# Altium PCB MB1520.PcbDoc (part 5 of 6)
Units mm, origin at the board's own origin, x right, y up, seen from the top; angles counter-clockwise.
Board outline 159 x 88 mm, 6 copper layers (Top Layer, Signal Layer 1, Signal Layer 2, Signal Layer 3, Signal Layer 4, Bottom Layer), stack 1.572 mm thick; 473 components, 377 nets, 1832 pads, 1378 vias.
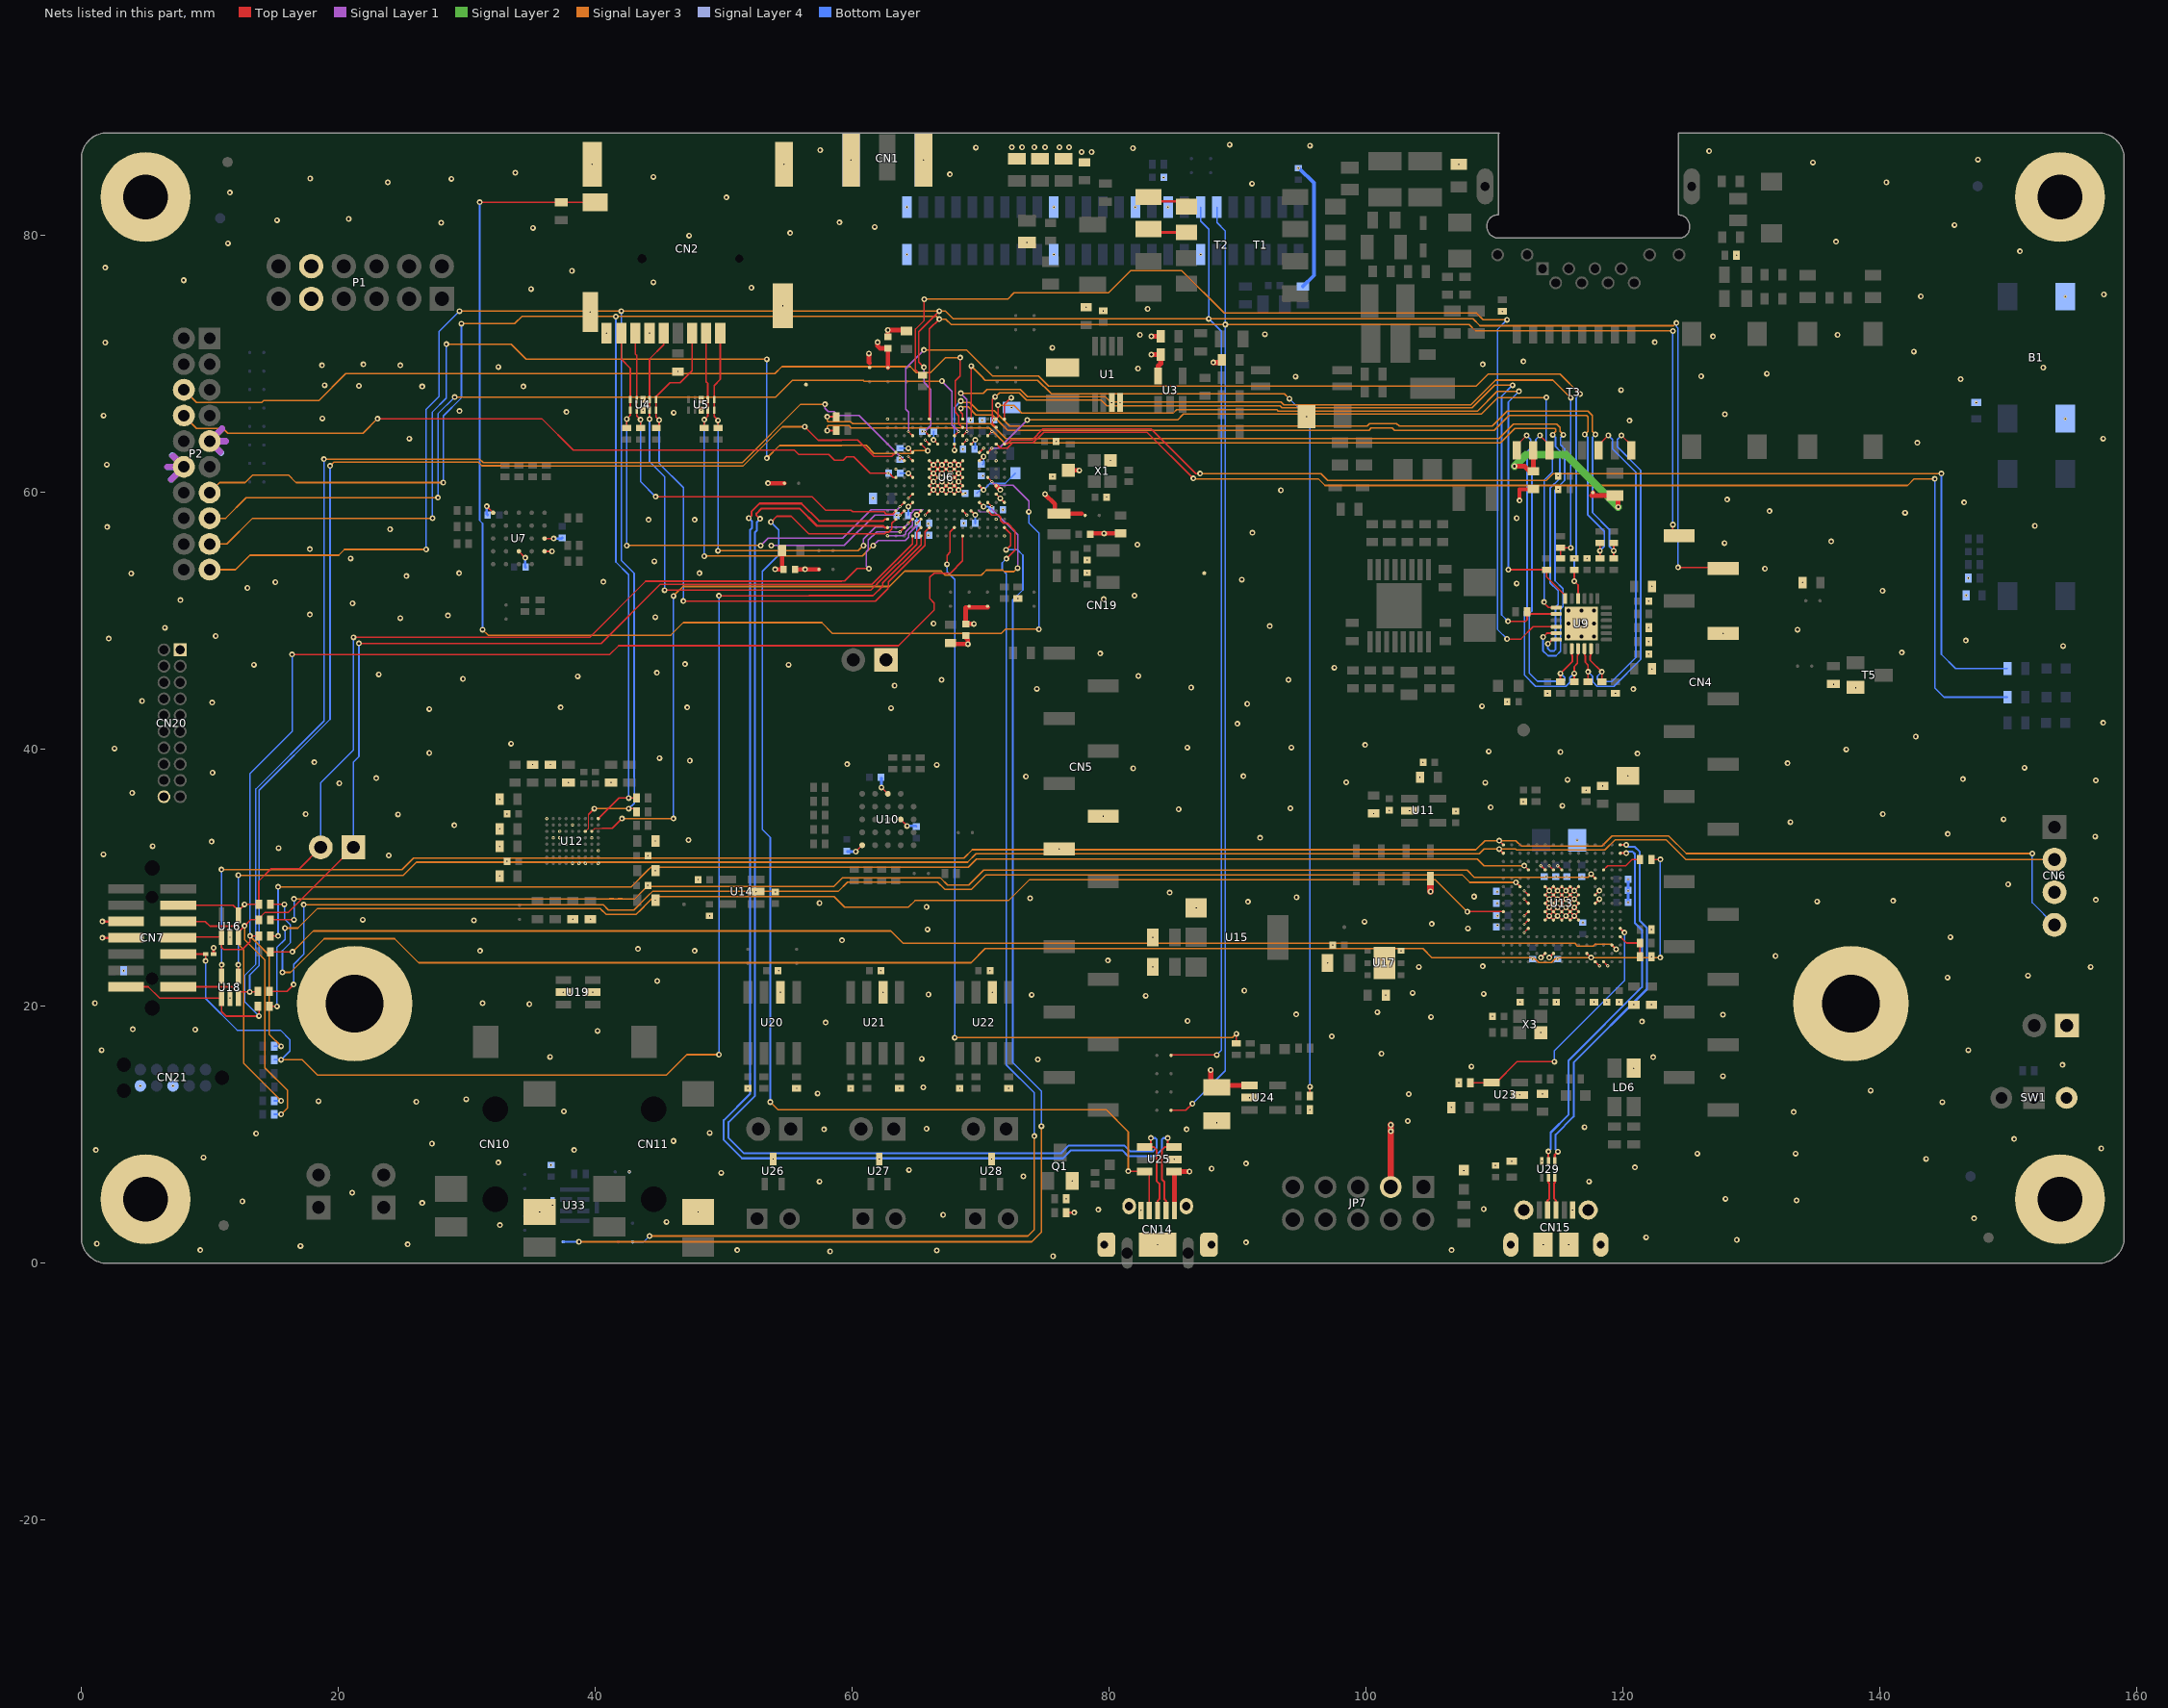
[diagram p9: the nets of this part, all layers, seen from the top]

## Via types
v1: diameter 0.45, hole 0.2, Top Layer to Bottom Layer, tented both sides, 1099 vias
v2: diameter 0.25, hole 0.1, Top Layer to Signal Layer 1, tented both sides, 217 vias
v3: diameter 0.25, hole 0.1, Signal Layer 4 to Bottom Layer, tented both sides, 53 vias
v4: diameter 0.6, hole 0.3, Top Layer to Bottom Layer, tented both sides, 9 vias

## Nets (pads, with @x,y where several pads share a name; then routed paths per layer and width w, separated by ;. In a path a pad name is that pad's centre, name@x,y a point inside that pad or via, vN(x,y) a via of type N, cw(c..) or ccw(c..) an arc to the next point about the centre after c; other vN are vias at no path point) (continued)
POE7: B1.1 B1.2 C3.1 C4.1 C5.1 C6.1 C11.1 C21.1 C22.1 C23.2 C24.2 C25.2 C26.1 C30.2 C32.1 C33.1 C34.2 C35.1 C36.2 C37.1 C38.1 C43.1 C44.1 C45.1 C46.2 C47.2 C48.1 C49.1 C50.1 C51.1 C53.1 C54.2 C55.2 C56.1 C61.2 C62.1 C63.1 C65.1 C66.1 C67.1 C70.1 C71.1 C72.1 C73.2 C74.1 C75.1 C76.1 C77.2 C78.2 C79.1 C80.1 C81.2 C82.2 C83.1 C84.1 C85.1 C86.2 C87.1 C88.1 C91.1 C92.1 C93.1 C94.1 C95.2 C96.1 C97.1 C98.1 C99.1 C100.1 C101.1 C102.1 C103.1 C104.1 C105.1 C106.1 C107.1 C108.1 C109.1 C110.1 C111.1 C112.2 C113.1 C114.1 C115.1 C116.2 C117.1 C120.1 C121.1 C122.1 C123.2 C124.1 C125.1 C126.1 C127.1 C128.1 C129.1 C130.2 C131.1 C132.1 C133.1 C134.1 C135.1 C136.1 C137.1 C139.1 C140.1 C141.1 C142.1 C143.1 C144.1 C145.1 C146.1 C147.1 C148.1 C149.1 C150.1 C151.1 C152.1 C153.1 C154.1 C155.1 C156.1 C157.1 C158.2 CN1.2 CN1.3 CN1.4 CN1.5 CN2.6 CN2.9 CN2.11 CN2.12 CN2.13 CN2.14 CN4.7 CN5.6 CN5.7 CN6.3 CN7.5 CN7.7 CN10.3 CN11.3 CN14.5 CN14.6 CN14.7 CN14.8 CN14.9 CN14.10 CN15.5 CN15.6 CN15.7 CN15.8 CN15.9 CN15.10 CN15.11 CN19.1 CN19.2 CN19.19 CN19.20 CN19.30 CN19.34 CN19.37 CN19.PTH1 CN19.PTH2 CN20.1 CN20.20 CN21.3 CN21.5 H1.1 H2.1 H3.1 H4.1 JP3.1 LD5.2 LD6.1 P1.5 P1.11 P2.5 P2.16 Q1.2 R1.2 R6.1 R13.1 R16.1 R19.2 R21.1 R57.2 R64.1 R70.2 R71.1 R73.2 R80.2 R84.1 R85.1 R89.1 R105.1 R109.1 R113.2 R120.2 R122.2 R124.2 R127.2 R129.1 R133.2 R137.1 R142.1 R146.1 SB35.1 SW1.3 T1.5 T1.6 T2.7 T2.8 T5.2 TP1.1 TP2.1 U1.7 U1.8 U3.5 U4.3 U4.8 U5.3 U5.8 U6.A1 U6.A15 U6.C2 U6.D6 U6.D10 U6.E1 U6.F2 U6.F6 U6.F7 U6.F8 U6.F9 U6.F10 U6.F12 U6.G6 U6.G7 U6.G8 U6.G9 U6.G10 U6.H6 U6.H7 U6.H8 U6.H9 U6.H10 U6.J6 U6.J7 U6.J8 U6.J9 U6.J10 U6.J14 U6.K2 U6.K6 U6.K7 U6.K8 U6.K9 U6.K10 U6.K12 U6.L4 U6.M6 U6.M10 U6.N3 U6.R1 U6.R15 U7.B1 U7.B3 U7.C1 U7.E5 U9.EP U10.B3 U10.C1 U10.E5 U11.2 U12.A1 U12.A3 U12.A4 U12.A5 U12.C1 U12.D6 U12.E2 U12.E7 U12.E8 U12.F7 U12.G5 U12.H9 U13.D5 U13.D6 U13.D7 U13.D8 U13.D9 U13.F2 U13.F6 U13.F7 U13.F8 U13.F9 U13.F10 U13.F12 U13.G2 U13.G6 U13.G7 U13.G8 U13.G9 U13.G10 U13.G12 U13.H6 U13.H7 U13.H8 U13.H9 U13.H10 U13.H12 U13.J6 U13.J7 U13.J8 U13.J9 U13.J10 U13.K6 U13.K7 U13.K8 U13.K9 U13.K10 U13.M1 U13.M8 U13.M9 U13.N1 U14.2 U15.1 U16.2 U17.6 U17.EP U18.2 U19.2 U19.5 U20.2 U21.2 U22.2 U23.2 U24.2 U25.2 U26.3 U27.3 U28.3 U29.3 U30.2 U31.2 U32.2 U33.5 U34.2 X1.2 X3.2 | length 138.7
  Top Layer w0.1: U6.R1@71.85,65.725 71.85,66.85 v1(72.375,67.375)
  Top Layer w0.12: v2(112.308,25.752) U13.D5@112.633,26.077 ; v2(112.308,26.402) U13.D6@112.633,26.727 ; v2(112.308,27.052) U13.D7@112.633,27.377 ; v2(112.308,28.352) U13.D8@112.633,28.027 ; v2(112.308,29.002) U13.D9@112.633,28.677 ; v1(113.608,23.802) U13.F2@113.933,24.127 ; v2(113.608,30.952) U13.F12@113.933,30.627 ; U13.F6@113.933,26.727 U13.G7@114.583,27.377 ; U13.F10@113.933,29.327 v1(114.258,29.002) U13.G9@114.583,28.677 ; v1(114.258,23.802) U13.G2@114.583,24.127 ; v2(114.258,30.952) U13.G12@114.583,30.627 ; v2(114.908,30.952) U13.H12@115.233,30.627 ; U13.K8@116.533,28.027 v1(116.208,28.352) U13.J9@115.883,28.677 ; U13.K10@116.533,29.327 U13.J9@115.883,28.677 ; U13.K6@116.533,26.727 v1(116.208,27.052) U13.J7@115.883,27.377 ; U13.K8@116.533,28.027 U13.J7@115.883,27.377 ; U13.M1@117.833,23.477 v2(118.158,23.152) ; U13.M8@117.833,28.027 v1(118.158,28.352) ; U13.M9@117.833,28.677 v1(118.158,29.002) ; U13.N1@118.483,23.477 v2(118.808,23.152) ; U13.G7@114.583,27.377 v1(114.908,27.052) U13.H6@115.233,26.727 U13.J7@115.883,27.377 ; U13.G7@114.583,27.377 v1(114.258,27.702) U13.F8@113.933,28.027 U13.G9@114.583,28.677 ; U13.G7@114.583,27.377 U13.H8@115.233,28.027 ; U13.G8@114.583,28.027 U13.F7@113.933,27.377 v1(114.258,27.052) U13.G6@114.583,26.727 U13.H7@115.233,27.377 ; U13.G8@114.583,28.027 v1(114.908,27.702) U13.H7@115.233,27.377 ; U13.G8@114.583,28.027 U13.H9@115.233,28.677 ; U13.G8@114.583,28.027 v1(114.258,28.352) U13.F9@113.933,28.677 U13.G10@114.583,29.327 v1(114.908,29.002) U13.H9@115.233,28.677 ; U13.G9@114.583,28.677 v1(114.908,28.352) U13.H8@115.233,28.027 ; U13.G9@114.583,28.677 U13.H10@115.233,29.327 v1(115.558,29.002) U13.J9@115.883,28.677 ; U13.H7@115.233,27.377 v1(115.558,27.052) U13.J6@115.883,26.727 U13.K7@116.533,27.377 v1(116.208,27.702) U13.J8@115.883,28.027 ; U13.H7@115.233,27.377 U13.J8@115.883,28.027 ; U13.H8@115.233,28.027 v1(115.558,27.702) U13.J7@115.883,27.377 ; U13.H8@115.233,28.027 U13.J9@115.883,28.677 ; U13.H9@115.233,28.677 v1(115.558,28.352) U13.J8@115.883,28.027 ; U13.H9@115.233,28.677 U13.J10@115.883,29.327 v1(116.208,29.002) U13.K9@116.533,28.677 U13.J8@115.883,28.027
  Top Layer w0.127: v1(31.55,58.925) U7.E5@32.05,58.425 ; U7.B3@34.05,55.425 v1(34.55,54.925) ; U7.B1@36.05,55.425 v1(36.625,55.425) ; U7.C1@36.05,56.425 v1(36.75,56.425) ; C47.2@54.55,54.125 C47.2@54.65,54.025 ; v1(60.275,32.05) U10.E5@60.775,32.55 ; v1(62.275,37.05) U10.C1@62.775,36.55 ; v2(62.745,56.629) U6.A15@62.75,56.625 ; U10.B3@63.775,34.55 v1(64.275,34.05) ; v2(64.375,59.55) U6.F12@64.7,59.875 ; v2(64.375,62.8) U6.K12@64.7,62.475 ; v2(65.675,58.25) U6.D10@66,58.575 ; v2(65.675,64.1) U6.M10@66,63.775 ; U6.F10@66,59.875 v1(66.325,60.2) ; U6.K10@66,62.475 v1(66.325,62.15) ; U6.F8@67.3,59.875 v1(66.975,60.2) ; U6.F8@67.3,59.875 v1(67.625,60.2) ; U6.G8@67.3,60.525 v1(67.625,60.2) ; U6.D6@68.6,58.575 v2(68.925,58.25) ; U6.F6@68.6,59.875 v1(68.275,60.2) ; U6.K6@68.6,62.475 v1(68.275,62.15) ; U6.M6@68.6,63.775 v2(68.925,64.1) ; U6.L4@69.9,63.125 v2(70.225,63.45) ; U6.N3@70.55,64.425 v2(70.875,64.75) ; U6.F2@71.2,59.875 v1(71.525,59.55) U6.E1@71.85,59.225 ; C43.1@78.525,56.75 C43.1@78.6,56.825 ; v1(66.325,60.2) U6.F9@66.65,59.875 v1(66.975,60.2) ; v1(66.325,60.2) U6.G10@66,60.525 v1(66.325,60.85) ; v1(66.325,60.2) U6.G9@66.65,60.525 ; v1(66.325,60.85) v1(66.975,61.5) ; v1(66.325,60.85) U6.G9@66.65,60.525 ; v1(66.325,60.85) U6.H10@66,61.175 v1(66.325,61.5) ; v1(66.325,61.5) v1(66.975,62.15) ; v1(66.325,61.5) U6.J10@66,61.825 v1(66.325,62.15) ; v1(66.325,61.5) v1(66.975,60.85) ; v1(66.325,62.15) U6.K9@66.65,62.475 v1(66.975,62.15) ; v1(66.325,62.15) v1(66.975,61.5) ; U6.G9@66.65,60.525 v1(66.975,60.85) ; U6.G9@66.65,60.525 v1(66.975,60.2) ; v1(66.975,60.2) U6.G8@67.3,60.525 ; v1(66.975,60.85) v1(67.625,61.5) ; v1(66.975,60.85) U6.G8@67.3,60.525 ; v1(66.975,61.5) v1(67.625,62.15) ; v1(66.975,61.5) v1(67.625,60.85) ; v1(66.975,62.15) v1(67.625,61.5) ; v1(66.975,62.15) U6.K8@67.3,62.475 v1(67.625,62.15) ; U6.G8@67.3,60.525 v1(67.625,60.85) ; v1(67.625,60.2) U6.F7@67.95,59.875 v1(68.275,60.2) ; v1(67.625,60.2) U6.G7@67.95,60.525 ; v1(67.625,60.85) U6.G7@67.95,60.525 ; v1(67.625,60.85) U6.H7@67.95,61.175 ; v1(67.625,61.5) U6.H7@67.95,61.175 ; v1(67.625,61.5) U6.J7@67.95,61.825 ; v1(67.625,62.15) U6.J7@67.95,61.825 ; v1(67.625,62.15) U6.K7@67.95,62.475 v1(68.275,62.15) ; U6.G7@67.95,60.525 v1(68.275,60.85) ; U6.G7@67.95,60.525 v1(68.275,60.2) ; U6.H7@67.95,61.175 v1(68.275,61.5) ; U6.H7@67.95,61.175 v1(68.275,60.85) ; U6.J7@67.95,61.825 v1(68.275,62.15) ; U6.J7@67.95,61.825 v1(68.275,61.5) ; v1(68.275,60.2) U6.G6@68.6,60.525 v1(68.275,60.85) ; v1(68.275,60.85) U6.H6@68.6,61.175 v1(68.275,61.5) ; v1(68.275,61.5) U6.J6@68.6,61.825 v1(68.275,62.15)
  Top Layer w0.2: v1(1.629,25.339) CN7.7@3.479,25.339 ; v1(1.629,26.609) CN7.5@3.479,26.609 ; U34.2@10.287,24.075 v1(10.287,24.563) ; T2.7@83.05,80.505 83.3,80.255 T1.6@86.023,80.255 ; T2.8@83.05,83.005 83.381,82.674 85.604,82.674 T1.5@86.023,82.255
  Top Layer w0.3: C25.2@88.547,70.125 C25.2@88.761,70.339 ; v1(111.95,59.375) 111.95,60.264 C33.1@113.011,60.264
  Top Layer w0.35: v1(54,54.025) C47.2@54.65,54.025 ; C47.2@54.55,54.125 C44.1@54.55,55.475 ; C23.2@62.775,72.125 v1(62.775,72.65) 64.15,72.65 C22.1@64.225,72.575 ; C53.1@67.65,48.3 67.55,48.2 v1(69,48.2) 69,48.55 68.85,48.7 C54.2@68.85,48.886 ; C43.1@78.6,56.825 C38.1@80.875,56.825
  Top Layer w0.4: v1(83.286,70.739) R21.1@84.011,70.739 84.011,70.036 83.811,69.836 U3.5@83.811,69.064 ; v1(83.286,72.164) R19.2@84.011,72.164 ; v1(88.1,70.125) C25.2@88.547,70.125
  Signal Layer 1 w0.09: 69.779,58.675 69.929,58.525 70.525,58.525
  Signal Layer 1 w0.1: v2@62.775,56.625 63.975,56.625 64.15,56.8 64.15,56.925 64.7,57.475 64.7,57.85 64.575,57.975 64.575,58.375 64.845,58.645 65.48,58.645 65.5,58.625
  Signal Layer 1 w0.5: 6.7,62 P2.16@7.975,62 ; 7,61.025 P2.16@7.975,62 ; 7.15,62.825 P2.16@7.975,62 ; 10.8,63.175 P2.5@9.975,64 ; 10.95,64.975 P2.5@9.975,64 ; 11.25,64 P2.5@9.975,64
  Signal Layer 4 w0.5: 6.75,62 P2.16@7.975,62 ; 7,61.025 P2.16@7.975,62 ; 7.075,62.9 P2.16@7.975,62 ; 10.875,63.1 P2.5@9.975,64 ; 10.95,64.975 P2.5@9.975,64 ; 11.2,64 P2.5@9.975,64
  Bottom Layer w0.127: C143.1@59.575,32.1 C143.1@59.625,32.05 ; C140.1@62.225,37.825 C140.1@62.275,37.775 ; C141.1@64.95,34.05 C141.1@65,34
  Bottom Layer w0.2: v1(31.55,58.925) 31.55,58.325 C132.1@31.625,58.25 ; v1(34.55,54.925) 34.55,54.215 C139.1@34.575,54.19 ; v1(36.75,56.425) 37.375,56.425 C136.1@37.425,56.475 ; C143.1@59.625,32.05 v1(60.275,32.05) ; v1(62.275,37.05) C140.1@62.275,37.775 ; v1(64.275,34.05) C141.1@64.95,34.05 ; v3(120.4,28.1) v3(120.4,29) C149.1@120.4,29.025 v3(120.4,29.875)
  Bottom Layer w0.3: v3(94.725,85.25) 94.78,85.25 95.925,84.105 95.925,76.9 R137.1@95.075,76.05
  other v1: 75.625,0.55 58.275,0.925 66.575,1 9.25,1.025 51.05,1.025 106.65,1.025 17.05,1.35 25.4,1.475 1.2,1.525 90.65,1.625 128.85,1.825 121.8,2.025 32.575,2.975 45.55,3.225 147.325,3.5 67.075,3.775 79.15,4.175 109.15,4.225 26.525,4.7 12.525,4.825 133.5,4.9 127.975,5.025 21.075,5.5 57.45,6.375 117.35,6.375 73.325,6.775 49.8,7.05 64.425,7.275 87.975,7.375 120.925,7.475 90.65,7.775 32.45,7.85 143.593,8.133 9.5,8.25 125.775,8.55 133.425,8.55 1.125,8.825 38.35,8.825 157.225,8.95 27.275,9.325 46.075,9.525 150.45,9.675 13.6,10.1 48.9,10.15 57.8,10.425 86.025,10.425 65.775,10.475 117,10.6 103.25,11.075 133.275,11.775 37.55,11.825 144.85,12.55 26.075,12.575 18.45,12.625 29.95,12.775 103.325,13.175 57.3,13.225 139.275,13.45 65.525,13.7 127.775,14.575 108.2,15.325 154.2,15.45 74.45,15.875 65.4,15.925 122.35,16.05 36.475,16.075 101.2,16.325 1.575,16.6 146.875,16.6 97.325,17.675 40.175,18.1 8.85,18.2 4,18.225 57.925,18.75 121.475,18.825 86.1,18.875 105.05,19.175 127.775,19.35 94.55,19.375 100.875,19.55 34.875,20.175 1.05,20.25 31.225,20.25 82.85,20.825 73.975,20.9 65.925,20.925 109.15,20.975 103.625,21.05 90.525,21.225 44.825,21.975 145.25,22.25 151.525,22.4 104.1,23.075 156.4,23.075 109.075,23.125 79.9,23.575 131.875,23.925 31.025,24.325 47.725,24.325 43.325,24.475 59.2,25.15 145.475,25.4 65.85,26 107.925,26.075 105.1,26.425 99.875,26.6 30.55,26.7 21.9,26.75 65.775,27.75 57.45,28.05 90.8,28.15 135.1,28.175 141.025,28.225 156.8,28.3 73.85,28.425 94.575,28.5 108.4,28.55 84.7,28.85 149.975,29.5 23.925,31.75 1.711,31.839 15.35,32.325 5.55,32.475 10.125,32.825 47.25,32.95 91.75,33.125 156.75,33.225 145.275,33.425 29.025,34.1 133.025,34.35 149.625,34.575 24.65,34.95 17.45,34.975 140.225,34.975 85.4,35.35 94.1,35.425 109.7,35.5 115.275,35.625 3.95,36.625 20.075,37.375 109.275,37.425 98.45,37.45 156.8,37.6 115.675,37.65 146.45,37.7 22.95,37.775 73.525,37.9 90.45,37.925 10.2,38.2 81.875,38.525 151.25,38.575 66.575,38.8 59.6,38.85 132.8,38.925 18.125,39 47.35,39.125 45,39.325 121.125,39.675 27.075,39.725 115.125,39.8 109.55,39.85 137.375,40 2.575,40.075 86.075,40.15 94.175,40.15 99.925,40.35 33.45,40.45 142.775,41 89.975,42 157.375,42.075 27.075,43.15 63.025,43.225 37.3,43.275 47.15,43.275 109.025,43.375 90.75,43.55 10.175,43.65 4.725,43.775 120.8,44.7 74.375,44.725 86.375,44.825 63.3,44.975 66.95,45.425 93.95,45.425 29.7,45.5 38.625,45.7 82.275,45.725 23.15,45.85 44.8,45.975 97.525,46.375 13.425,46.6 55.05,46.6 46.975,46.65 79.3,47.475 141.7,47.55 154.25,48.05 146.675,48.475 2.125,48.625 10.45,48.825 133.575,49.325 6.5,49.475 92.5,49.6 66.325,49.8 24.825,50.225 44.675,50.3 28.525,50.425 17.775,50.5 21.1,51.375 7.7,51.625 79.575,51.7 81.975,51.975 140.2,52.35 12.925,52.575 111.725,52.925 15.1,53.025 40.625,53.05 90.325,53.225 25.3,53.5 3.875,53.7 29.4,53.725 48.1,53.725 131.05,54.075 44.6,54.65 20.95,54.875 17.775,55.6 82.2,55.95 127.9,56.075 136.2,56.2 79.6,56.825 91.15,56.875 24.025,57.15 2,57.325 152.05,57.4 44.15,57.875 47.725,57.875 111.725,58 141.95,58.425 131.4,58.55 146.55,59.225 128.1,59.45 93.375,60.175 1.975,62.175 142.9,63.875 25.525,64.2 157.375,64.2 120.5,65.6 18.75,65.775 1.725,66 127.925,66.1 46.1,66.225 37.75,66.275 29.425,66.35 119.85,67.975 26.525,68.25 34.4,68.25 21.6,68.3 18.925,68.35 146.275,68.825 94.5,69.025 126.075,69.05 131.2,69.25 82.25,69.65 152.7,69.725 32.45,69.775 18.725,69.9 24.825,69.9 21.95,69.975 109.075,69.975 112.25,70.2 142.625,70.975 75.575,71.275 1.85,71.675 122.475,71.7 127,72.15 82.4,72.275 136.7,72.275 92.125,72.325 83,74.3 143.175,75.275 157.425,75.425 35,75.85 52.15,75.95 44.525,76.375 7.95,76.525 38.175,77.25 1.85,77.5 150.9,78.775 11.4,79.4 136.575,79.525 47.3,80 55.175,80.2 35.15,80.6 61.75,80.675 145.8,80.825 28,81 59,81.025 15.225,81.2 20.8,81.3 50.2,82.975 11.55,83.35 91.125,84.05 23.85,84.15 140.5,84.15 28.8,84.425 17.8,84.45 44.525,84.575 67.6,84.775 33.775,84.9 134.775,85.7 147.625,85.925 77.85,86.5 78.625,86.5 126.7,86.575 57.5,86.65 81.85,86.8 69.625,86.85 72.425,86.875 73.225,86.875 74.175,86.875 75,86.875 76.125,86.875 76.875,86.875 95.625,87 89.375,87.075
  other v2: 83.775,1.45 113.775,1.45 115.775,1.45 35.675,4 48,4 82.475,4.125 116.075,4.15 76.65,5.025 77.125,6.425 107.611,7.227 110.061,7.614 111.336,7.964 113.686,7.964 85.05,8.1 53.85,8.125 62.1,8.125 70.85,8.125 88.375,10.937 95.625,11.95 106.636,12.139 90.925,12.9 111.961,13.114 113.725,13.2 51.875,13.625 55.675,13.625 59.875,13.625 63.675,13.625 68.375,13.625 72.175,13.625 107.211,14.064 120.836,15.189 113.611,17.964 109.836,19.214 120.836,20.139 122.211,20.139 111.986,20.339 114.811,20.339 117.736,20.339 118.736,20.339 119.686,20.339 11.561,20.639 101.525,20.875 37.5,21.1 39.8,21.1 54.41,21.1 62.41,21.1 70.91,21.1 54.275,22.775 62.225,22.775 70.725,22.775 83.4,23.075 97,23.375 101.425,23.375 122.211,23.864 102.725,24.325 97.4,24.775 83.4,25.375 11.561,25.389 122.211,25.989 38.25,26.8 39.625,26.8 48.9,27.05 86.775,27.675 44.675,28.275 54.025,28.9 52.525,28.925 44.1,29.425 48,29.875 32.55,30.15 44.675,30.575 38.225,31.125 38.725,31.125 39.225,31.125 40.225,31.125 33.125,31.3 44.1,31.725 40.225,32.125 76.112,32.26 32.55,32.45 37.725,32.625 44.675,32.875 36.725,33.125 37.225,33.125 39.725,33.125 37.225,33.625 32.55,33.825 38.225,34.125 36.225,34.625 79.541,34.8 33.125,34.975 100.586,35.014 106.986,35.189 103.386,35.239 101.811,35.264 112.236,35.939 32.55,36.125 117.111,36.839 118.411,37.164 37.9,37.425 41.225,37.425 104.186,37.839 120.381,37.95 35.125,38.825 36.5,38.825 104.436,38.989 110.975,43.725 114.125,44.375 119.4,44.375 138.111,44.814 136.386,45.064 122.25,46.275 122,47.425 122,48.4 127.8,49.024 122,49.475 122,51.55 72.9,51.75 122.25,52.7 133.975,53 78.275,53.75 78.275,54.75 116.2,54.875 117.2,54.875 71.85,56.625 71.2,57.925 79.8,59.65 114.95,60.25 75.6,61.25 114.95,61.3 63.4,61.825 71.2,62.475 80.1,62.5 75.875,63.975 62.75,65.725 95.359,65.91 43.725,66.415 48.25,66.415 80.2,67 80.85,67 43.725,67.235 48.25,67.235 46.425,69.425 40.875,72.4 44.225,72.4 39.6,74.05 110.6,74.1 79.536,74.139 78.211,74.439 54.6,74.55 128.832,78.483 73.611,79.464 39.75,85.55 54.7,85.55 107.211,85.539 59.9,85.9 65.55,85.9
  other v3: 36.674,4.523 42.649,7.123 36.549,7.648 4.585,13.815 7.125,13.815 3.286,22.789 112.975,23.675 114.9,23.675 110.225,26.325 116.875,26.525 110.225,27.05 110.211,28.014 110.211,28.914 114,30.1 114.8,30.1 115.6,30.1 116.8,30.1 116.425,32.925 146.7,52 146.875,53.35 65.925,56.675 65.925,57.575 68.675,57.6 63.45,58.225 71.725,58.65 61.625,59.55 68.8,59.95 70.175,61.3 62.825,61.5 63.7,62.55 68.625,63.375 65.45,64.775 69.2,65.625 70.125,65.625 71.025,65.625 154.425,65.75 72.4,66.625 147.5,67 154.425,75.25 64.26,78.531 75.69,78.531 87.12,78.531 64.26,82.217 75.69,82.217 82.04,82.217 84.58,82.217 84.25,84.525 59.9,85.9 65.55,85.9
  other v4: 115.75,48.8 116.75,48.8 117.75,48.8 115.75,49.8 116.75,49.8 117.75,49.8 115.75,50.8 116.75,50.8 117.75,50.8
RD_N: R78.1 T3.8 U9.22 | length 28.2
  Top Layer w0.13: U9.22@117,47.85 117,47.36 117.059,47.3 117.059,46.792 117.275,46.577 v1(117.275,46.05) R78.1@117.275,45.275 ; v1(119.875,64.45) 120.631,63.694 T3.8@120.631,63.279
  Bottom Layer w0.13: v1(117.275,46.05) 117.622,45.703 117.622,45.289 117.992,44.919 119.283,44.919 121.375,47.011 121.375,61.735 119.552,63.558 119.552,64.127 v1(119.875,64.45)
RD_P: R79.1 T3.6 U9.23 | length 27.2
  Top Layer w0.13: U9.23@117.5,47.85 117.5,47.36 117.44,47.3 117.44,46.95 v1(118.35,46.04) R79.1@118.35,45.275 ; T3.6@118.091,63.279 118.091,63.694 v1(118.848,64.45)
  Bottom Layer w0.13: v1(118.35,46.04) 118.003,45.693 118.003,45.447 118.15,45.3 119.125,45.3 120.994,47.169 120.994,61.577 119.171,63.4 119.171,64.127 v1(118.848,64.45)
RMII_CRS_DV: R51.2 R56.1 U6.N6 | length 66.4
  Top Layer w0.12: R56.1@115.125,54.875 R51.2@115.125,55.7 v1(115.925,55.7)
  Top Layer w0.127: U6.N6@68.6,64.425 v2(68.925,64.75)
  Signal Layer 1 w0.1: v1(68.45,67.725) 68.925,67.25 v2(68.925,64.75)
  Signal Layer 3 w0.1: v1(68.45,67.725) 70.175,67.725 70.475,68.025 73.061,68.025 73.636,67.45 75.425,67.45
  Signal Layer 3 w0.12: 75.425,67.45 79.7,67.45 80.1,67.05 93.375,67.05 93.594,66.831 108.154,66.831 110.078,68.755 114.545,68.755 v1(115.925,67.375)
  Bottom Layer w0.12: v1(115.925,55.7) v1(115.925,67.375)
RMII_MDC: U6.L3 U9.13 | length 62.8
  Top Layer w0.12: v1(113.85,51.475) 113.85,51.398 114.198,51.05 U9.13@114.8,51.05
  Top Layer w0.127: U6.L3@70.55,63.125 v2(70.875,63.45)
  Signal Layer 1 w0.1: v2(70.875,63.45) 71.425,63.45 v1(73.625,65.65)
  Signal Layer 3 w0.1: v1(73.625,65.65) 75.425,65.65
  Signal Layer 3 w0.12: 75.425,65.65 85.325,65.65 85.78,66.105 108.98,66.105 110.275,67.4 v1(114.025,67.4)
  Bottom Layer w0.12: v1(113.85,51.475) 113.85,60.95 114.5,61.6 114.5,62.575 114.025,63.05 v1(114.025,67.4)
RMII_MDIO: R55.1 U6.R2 U9.12 | length 62.7
  Top Layer w0.1: U6.R2@71.2,65.725 71.35,65.875 v1(71.35,66.8)
  Top Layer w0.12: v1(111.075,54) 114.025,54 R55.1@114.05,53.975 114.05,53.431 115.5,51.981 U9.12@115.5,51.75
  Signal Layer 3 w0.1: v1(71.35,66.8) 72.6,66.8 73.2,66.2 75.425,66.2
  Signal Layer 3 w0.12: 75.425,66.2 85,66.2 85.25,66.45 93.05,66.45 93.155,66.345 108.67,66.345 110.2,67.875 v1(111.9,67.875)
  Bottom Layer w0.12: v1(111.075,54) 111.075,67.05 v1(111.9,67.875)
RMII_REF_CLK: R67.2 U6.P2 U9.14 | length 67.7
  Top Layer w0.1: v1(71.125,67.45) 70.9,67.225 70.9,65.375 U6.P2@71.2,65.075
  Top Layer w0.127: v1(111.048,49.975) 112.425,49.975 112.525,50.075 R67.2@112.525,50.725 112.7,50.55 U9.14@114.8,50.55
  Signal Layer 3 w0.1: v1(71.125,67.45) 71.45,67.775 73,67.775 73.579,67.196
  Signal Layer 3 w0.102: 73.579,67.196 79.354,67.196 79.8,66.75 93.3,66.75 93.45,66.6 108.25,66.6 110,68.35 v1(111.4,68.35)
  Bottom Layer w0.127: v1(111.048,49.975) 110.55,50.473 110.55,67.5 v1(111.4,68.35)
RMII_RX_ER: R57.1 U6.N12 U9.10 | length 77.9
  Top Layer w0.12: R57.1@116.2,53.975 v1(116.2,53.1) 116.5,52.8 U9.10@116.5,51.75
  Top Layer w0.127: v2(64.375,64.75) U6.N12@64.7,64.425
  Signal Layer 1 w0.1: v2(64.375,64.75) 64.375,66.275 64.155,66.495 64.155,69.68 v1(65.575,71.1)
  Signal Layer 3 w0.1: 74.5,69.075 75.3,68.275 75.425,68.275
  Signal Layer 3 w0.12: v1(65.575,71.1) 68.9,71.1 70.925,69.075 74.5,69.075 ; 75.425,68.275 108.55,68.275 109.5,69.225 115.1,69.225 v1(116.65,67.675)
  Bottom Layer w0.12: v1(116.2,53.1) 116.2,54.925 116.35,55.075 116.35,67.375 v1(116.65,67.675)
RMII_RXD0: R49.1 R58.1 U6.R6 | length 63.7
  Top Layer w0.1: v1(68.45,66.55) 68.45,66.275 68.6,66.125 U6.R6@68.6,65.725
  Top Layer w0.13: R58.1@118.2,54.875 v1(118.2,55.475) R49.1@118.2,56.075
  Signal Layer 3 w0.104: v1(68.45,66.55) 68.572,66.672 69.025,66.672 69.647,66.05 70.9,66.05 72.106,64.844 100.212,64.844 100.393,65.025 102.019,65.025 102.2,64.844 109.962,64.844 111.118,66 117.15,66 117.269,65.881 117.269,64.775 v1(117.019,64.525)
  Bottom Layer w0.13: v1(117.019,64.525) 117.244,64.3 117.244,58.281 118.547,56.978 118.547,55.822 v1(118.2,55.475)
RMII_RXD1: R50.1 R59.1 U6.M7 | length 67.9
  Top Layer w0.1: v1(67.95,63.3) U6.M7@67.95,63.775
  Top Layer w0.13: R59.1@119.275,54.875 v1(119.275,55.475) R50.1@119.275,56.075
  Signal Layer 3 w0.104: v1(68.45,67.125) 68.572,67.003 69.162,67.003 69.784,66.381 71.037,66.381 72.243,65.175 100.075,65.175 100.275,65.375 102.375,65.375 102.575,65.175 109.825,65.175 110.981,66.331 117.287,66.331 117.6,66.018 117.6,64.775 v1(117.85,64.525)
  Bottom Layer w0.1: v1(67.95,63.3) 67.95,66.615 67.965,66.631 67.965,66.64 v1(68.45,67.125)
  Bottom Layer w0.13: v1(117.85,64.525) 117.625,64.3 117.625,58.439 118.928,57.136 118.928,55.822 v1(119.275,55.475)
RMII_TX_EN: R24.1 U9.16 | length 84.2
  Top Layer w0.12: R24.1@65.475,69.125 65.35,69.125 64.925,69.55 64.925,72.725 65.6,73.4 v1(65.6,75.05) ; v1(110.975,48.6) 112.05,48.6 113,49.55 U9.16@114.8,49.55
  Signal Layer 3 w0.12: v1@65.689,75.139 v1(65.6,75.05) 72.1,75.05 72.6,75.55 79.95,75.55 81.675,77.275 85.65,77.275 88.95,73.975 108.575,73.975 109.1,73.45 v1(110.975,73.45)
  Bottom Layer w0.12: v1(110.975,48.6) 110.216,49.359 110.216,72.691 v1(110.975,73.45)
RMII_TXD0: R25.1 U9.17 | length 81.5
  Top Layer w0.13: v1(58.05,65.9) R25.1@58.75,65.9 ; v1(113.775,48.75) 114.075,49.05 U9.17@114.8,49.05
  Signal Layer 3 w0.104: v1(58.05,65.9) 58.05,65.603 58.125,65.528 59.865,65.528 60.034,65.359 70.809,65.359 71.962,64.206 110.331,64.206 111.456,65.331 114.837,65.331 115.106,65.062 115.106,64.75 v1(115.356,64.5)
  Bottom Layer w0.13: v1(113.775,48.75) 113.76,48.735 113.76,47.701 114.167,47.294 114.783,47.294 115.131,47.642 115.131,50.931 115.331,51.131 115.331,52.508 115.325,52.514 114.703,53.136 114.703,60.189 115.456,60.942 115.456,63.394 115.131,63.719 115.131,64.275 v1(115.356,64.5)
RMII_TXD1: R32.1 U9.18 | length 78.8
  Top Layer w0.13: v1(58.05,64.825) R32.1@58.75,64.825 ; v1(114.15,48.225) 114.475,48.55 U9.18@114.8,48.55
  Signal Layer 3 w0.104: v1(58.05,64.825) 58.05,65.122 58.125,65.197 59.728,65.197 59.897,65.028 70.672,65.028 71.825,63.875 110.468,63.875 111.593,65 114.7,65 114.775,64.925 114.775,64.75 v1(114.525,64.5)
  Bottom Layer w0.13: v1(114.15,48.225) 114.15,47.85 114.325,47.675 114.625,47.675 114.75,47.8 114.75,51.089 114.95,51.289 114.95,52.35 114.322,52.978 114.322,60.347 115.075,61.1 115.075,63.236 114.75,63.561 114.75,64.275 v1(114.525,64.5)
SAI1_SD_A: U6.E3 U12.F2 | length 58.2
  Top Layer w0.09: U12.F2@39.725,33.625 39.975,33.875 40.55,33.875
  Top Layer w0.1: 40.55,33.875 41.325,33.875 v1(42.075,34.625)
  Top Layer w0.127: U6.E3@70.55,59.225 v2(70.875,58.9)
  Signal Layer 1 w0.1: v2(70.875,58.9) 70.875,58.7 72.875,56.7 v1(72.875,54.125)
  Signal Layer 3 w0.1: v1(42.075,34.625) 44.1,34.625
  Signal Layer 3 w0.12: 44.1,34.625 v1(46.075,34.625) ; v1(46.075,51.95) 46.814,52.689 62.889,52.689 64.085,53.885 66.92,53.885 67.23,53.575 70.05,53.575 70.435,53.96 71.715,53.96 71.83,53.845 72.595,53.845 v1(72.875,54.125)
  Bottom Layer w0.12: v1(46.075,34.625) v1(46.075,51.95)
SAI4_CK2: SB40.2 U6.D3 | length 90.4
  Top Layer w0.1: U6.D3@70.55,58.575 70.875,58.25 71.375,58.25 71.525,58.1 71.525,57.825 71.75,57.6 72.1,57.6 72.675,57.025 72.675,55.525 v1(72,54.85)
  Signal Layer 3 w0.12: v1(44.225,2.125) 73.675,2.125 74.175,2.625 v1(74.175,9.9)
  Bottom Layer w0.12: SB40.2@42.899,1.673 43.773,1.673 v1(44.225,2.125) ; v1(72,54.85) 71.675,54.525 71.675,54 71.998,53.676 71.998,15.452 74.175,13.275 v1(74.175,9.9)
SAI4_D2: SB39.2 U6.B1 | length 95
  Top Layer w0.1: U6.B1@71.85,57.275 72.325,56.8 72.325,55.9 v1(71.975,55.55)
  Signal Layer 3 w0.12: v1(38.725,1.675) 73.975,1.675 74.725,2.425 v1(74.725,10.675)
  Bottom Layer w0.12: SB39.2@37.5,1.675 v1(38.725,1.675) ; v1(71.975,55.55) 72.85,55.55 73.28,55.12 73.28,52.429 72.5,51.649 72.5,15.625 74.725,13.4 v1(74.725,10.675)
SCL: CN4.10 CN19.40 P2.7 R90.1 SB34.1 U6.R10 U12.H1 | length 265.7
  Top Layer w0.1: U12.H1@40.225,34.625 41.825,36.225 v1(42.6,36.225) R90.1@43.2,36.225 ; U6.R10@66,65.725 66.009,65.734 66.009,69.075
  Top Layer w0.12: 66.009,69.075 66.009,72.734 v1(66.775,73.5) ; SB34.1@84.811,11.914 85.964,11.914 v1(86.475,12.425) ; v1(123.875,57.5) 123.875,57.142 CN4.10@124.372,56.644
  Signal Layer 3 w0.12: P2.7@9.975,60 10.75,60.775 12.75,60.775 13.325,61.35 16.125,61.35 16.7,60.775 v1(28.167,60.775) ; v1(29.575,73.15) 33.725,73.15 34.3,73.725 41.72,73.725 41.725,73.72 66.555,73.72 v1(66.775,73.5) 67.275,73.5 67.695,73.08 v1(89.038,73.08) 108.02,73.08 108.52,72.58 v1(123.875,72.58)
  Bottom Layer w0.1: v1@42.6,36.25 42.6,37.8
  Bottom Layer w0.12: v1(28.167,60.775) 28.167,65.967 29.575,67.375 v1(29.575,73.15) ; v1(41.6,73.7) 41.6,54.6 42.6,53.6 42.6,37.8 ; v1(86.475,12.425) 89.038,14.988 v1(89.038,73.08) 89.038,80.361 88.39,81.009 CN19.40@88.39,82.217 ; v1(123.875,57.5) v1(123.875,72.58)
SDA: CN4.9 CN19.38 P2.10 R92.1 SB31.1 U6.N10 U12.F3 | length 281.2
  Top Layer w0.09: U12.F3@39.225,33.625 39.475,33.875 39.475,34.95
  Top Layer w0.1: 39.475,34.95 v1(39.925,35.4) ; v1(42.6,35.4) R92.1@43.2,35.4
  Top Layer w0.12: v1(65.575,69.75) 65.17,70.155 65.17,72.52 v1(66.775,74.125) ; SB31.1@84.811,16.189 84.847,16.225 v1(88.375,16.225) ; v1(124.28,54.17) 127.576,54.17 127.721,54.025 CN4.9@127.8,54.104
  Top Layer w0.127: v2(65.675,64.75) U6.N10@66,64.425
  Signal Layer 1 w0.1: v1(65.575,69.75) 65.575,68.575 66.125,68.025 66.125,65.2 v2(65.675,64.75)
  Signal Layer 3 w0.1: v1(39.925,35.4) v1(42.6,35.4)
  Signal Layer 3 w0.12: P2.10@9.975,54 12,54 13.125,55.125 16.298,55.125 20.025,55.125 20.475,55.575 v1(26.825,55.575) ; v1(29.425,74.125) v1(66.775,74.125) 67.25,74.125 67.85,73.525 v1(87.753,73.525) 108.326,73.525 108.866,72.985 123.935,72.985 v1(124.15,73.2)
  Bottom Layer w0.1: v1(42.6,35.4) 43.025,35.825 43.025,37.8
  Bottom Layer w0.12: v1(26.825,55.575) 26.825,66.475 27.85,67.5 27.85,72.55 v1(29.425,74.125) ; v1(42.025,74.125) 42.025,54.714 43.025,53.714 43.025,37.8 ; CN19.38@87.12,82.217 87.12,81.129 87.753,80.496 v1(87.753,73.525) 88.73,72.548 88.73,16.58 v1(88.375,16.225) ; v1(124.15,73.2) 124.15,72.93 124.28,72.8 v1(124.28,54.17)
SDIO1_CK: CN2.5 U4.2 U4.9 U6.B11 | length 43.5
  Top Layer w0.1: 61.929,52.879 65.025,55.975 65.025,56.95 U6.B11@65.35,57.275
  Top Layer w0.127: v1(44.225,65.725) U4.9@44.225,66.415 U4.2@44.225,67.235 44.225,70.4 45.325,71.5 CN2.5@45.325,72.4 ; v1(45.4,52.4) 61.45,52.4 61.929,52.879
  Bottom Layer w0.127: v1(44.225,65.725) 44.225,62.4 45.4,61.225 v1(45.4,52.4)
SDIO1_CMD: CN2.3 R29.1 U4.1 U4.10 U6.B10 | length 46.5
  Top Layer w0.1: 62.804,52.625 62.804,53.029 65.675,55.9 65.675,56.95 U6.B10@66,57.275
  Top Layer w0.127: R29.1@44.75,65.025 44.975,65.25 v1(44.975,65.65) 44.725,65.9 U4.10@44.725,66.415 U4.1@44.725,67.235 44.725,67.45 45.825,68.55 46.6,68.55 47.525,69.475 CN2.3@47.525,72.4 ; v1(46.854,51.546) 61.804,51.546 62.783,52.525 62.783,52.604 62.804,52.625
  Bottom Layer w0.127: v1(44.975,65.65) 44.975,62.254 46.854,60.375 v1(46.854,51.546)
SDIO1_D0: CN2.7 R28.1 U4.4 U4.7 U6.D14 | length 33.4
  Top Layer w0.1: 59.167,58.633 59.91,58.633 60.042,58.5 62.464,58.5 62.644,58.32 63.145,58.32 U6.D14@63.4,58.575
  Top Layer w0.127: CN2.7@43.125,72.4 43.125,70.775 43.225,70.675 U4.4@43.225,67.235 U4.7@43.225,66.415 43.225,65.975 v1(43.525,65.675) R28.1@43.525,65.025 ; v1(44.7,59.675) 56.884,59.675 57.926,58.633 59.167,58.633
  Bottom Layer w0.127: v1(43.525,65.675) 43.525,60.85 v1(44.7,59.675)
SDIO1_D1: CN2.8 R27.1 U4.5 U4.6 U6.E13 | length 40.6
  Top Layer w0.127: CN2.8@42.025,72.4 42.025,70.375 42.725,69.675 U4.5@42.725,67.235 U4.6@42.725,66.415 42.725,66 v1(42.45,65.725) R27.1@42.45,65.025 ; v2(63.725,58.9) U6.E13@64.05,59.225
  Signal Layer 1 w0.1: v1(52.875,55.875) 53.45,56.45 59.275,56.45 61.475,58.65 63.475,58.65 v2(63.725,58.9)
  Signal Layer 3 w0.102: v1(42.45,55.875) v1(52.875,55.875)
  Bottom Layer w0.127: v1(42.45,55.875) v1(42.45,65.725)
SDIO1_D2: CN2.1 R31.1 U5.1 U5.10 U6.C12 | length 34.3
  Top Layer w0.127: R31.1@49.55,65.025 v1(49.55,65.625) 49.25,65.925 U5.10@49.25,66.415 U5.1@49.25,67.235 49.25,68.325 49.725,68.8 CN2.1@49.725,72.4 ; v2(64.375,57.6) U6.C12@64.7,57.925
  Signal Layer 1 w0.1: v1(60.875,55.875) 60.875,56.378 61.822,57.325 64.1,57.325 v2(64.375,57.6)
  Signal Layer 3 w0.1: 59.175,55.473 60.473,55.473 v1(60.875,55.875)
  Signal Layer 3 w0.102: v1(49.55,55.473) 59.175,55.473
  Bottom Layer w0.127: v1@49.55,55.473 v1(49.55,65.625)
SDIO1_D3: CN2.2 R30.1 U5.2 U5.9 U6.C11 | length 36.5
  Top Layer w0.127: R30.1@48.475,65.025 v1(48.475,65.675) 48.75,65.95 U5.9@48.75,66.415 U5.2@48.75,67.235 48.75,68.5 48.625,68.625 CN2.2@48.625,72.4 ; v2(65.025,57.6) U6.C11@65.35,57.925
  Signal Layer 1 w0.1: v1(61.625,55.875) 62.027,56.277 64.136,56.277 64.378,56.519 64.378,56.784 65.025,57.431 v2(65.025,57.6)
  Signal Layer 3 w0.1: 59.175,55.05 60.8,55.05 v1(61.625,55.875)
  Signal Layer 3 w0.102: v1(48.475,55.05) 59.175,55.05
  Bottom Layer w0.127: v1(48.475,55.05) v1(48.475,65.675)
STLK_SWCLK: CN6.2 U13.A14 U18.4 | length 151.6
  Top Layer w0.12: U18.4@12.211,22.339 v1(12.211,23.236) ; v1(110.358,32.252) U13.A14@110.683,31.927
  Signal Layer 3 w0.12: v1(12.211,30.211) 25.061,30.211 26.075,31.225 33.2,31.225 44.1,31.225 68.975,31.225 69.625,31.875 108.8,31.875 109.177,32.252 109.908,32.252 v1(110.358,32.252) 111.623,32.252 111.7,32.175 118.586,32.175 119.386,32.975 120.558,32.975 123.35,32.975 124.898,31.427 CN6.2@153.581,31.427
  Bottom Layer w0.12: v1(12.211,23.236) v1(12.211,30.211)
STLK_SWDIO: CN6.4 U13.A15 U18.5 | length 158
  Top Layer w0.12: U18.5@10.911,22.339 v1(10.911,23.236) ; v1(110.358,32.902) U13.A15@110.683,32.577
  Signal Layer 3 w0.12: v1(10.9,30.65) 24.95,30.65 25.85,31.55 33.2,31.55 44.1,31.55 68.7,31.55 69.35,32.2 108.55,32.2 109.252,32.902 109.908,32.902 v1(110.358,32.902) 111.66,32.902 112.087,32.475 118.35,32.475 119.15,33.275 120.558,33.275 123.55,33.275 124.925,31.9 v1(151.85,31.9)
  Bottom Layer w0.12: v1(10.9,30.65) 10.911,30.639 v1(10.911,23.236) ; v1(151.85,31.9) 151.85,28.078 CN6.4@153.581,26.347
STLK_VCP_RX: R110.2 U13.C10 | length 105.5
  Top Layer w0.12: R110.2@14.625,21.175 16,21.175 v1(16.525,21.7) ; v1(111.658,29.652) U13.C10@111.983,29.327
  Signal Layer 3 w0.12: v1(17.3,27.925) 33.2,27.925 40.6,27.925 41.025,27.5 43,27.5 44.1,28.6 44.45,28.95 58.9,28.95 59.63,29.68 66.645,29.68 67.2,29.125 69.3,29.125 70.425,30.25 107.475,30.25 108.073,29.652 109.908,29.652 v1(111.658,29.652)
  Bottom Layer w0.12: v1(16.525,21.7) 16.525,23.275 17.3,24.05 v1(17.3,27.925)
STLK_VCP_TX: R114.1 U13.A7 | length 105.4
  Top Layer w0.12: R114.1@14.625,20 v1(15.225,20) ; v1(107.873,27.377) U13.A7@110.683,27.377
  Signal Layer 3 w0.12: v1(15.85,26.1) 16.85,26.1 18.35,27.6 33.2,27.6 40.4,27.6 40.5,27.5 40.825,27.175 43.2,27.175 43.525,27.5 44.1,28.075 44.575,28.55 58.575,28.55 59.4,27.725 64.375,27.725 64.889,28.239 72.164,28.239 73.775,29.85 105.4,29.85 v1(107.873,27.377)
  Bottom Layer w0.12: v1(15.225,20) 15.225,24.6 15.85,25.225 v1(15.85,26.1)
STMOD#8-MOSIs: P2.8 U6.N7 | length 70.2
  Top Layer w0.127: U6.N7@67.95,64.425 v2(68.275,64.75)
  Signal Layer 1 w0.1: v1(66.975,68.675) 67.775,67.875 67.775,65.25 v2(68.275,64.75)
  Signal Layer 3 w0.12: P2.8@9.975,58 11.225,58 12.825,59.6 v1(27.75,59.6) ; v1(29.05,67.425) 54.025,67.425 55.336,68.736 60.864,68.736 60.925,68.675 v1(66.975,68.675)
  Bottom Layer w0.12: v1(27.75,59.6) 27.75,66.125 v1(29.05,67.425)
STMOD#9-MISOs: P2.9 U6.M11 | length 79.3
  Top Layer w0.127: U6.M11@65.35,63.775 v1(65.875,63.25)
  Signal Layer 3 w0.1: 59.175,63.662 61.088,63.662 61.695,63.055 64.63,63.055 64.825,63.25 v1(65.875,63.25)
  Signal Layer 3 w0.12: P2.9@9.975,56 11.325,56 13.325,58 v1(27.325,58) ; v1(28.4,71.55) 33.45,71.55 34.625,70.375 v1(53.35,70.375) ; v1(53.35,62.675) 54.337,63.662 59.175,63.662
  Bottom Layer w0.12: v1(27.325,58) 27.325,66.275 28.4,67.35 v1(28.4,71.55) ; v1(53.35,62.675) v1(53.35,70.375)
STMOD#13-ADC: P2.13 U6.P6 | length 68.5
  Top Layer w0.1: 68.406,69.075 68.025,68.694 68.025,66.25 68.3,65.975 68.3,65.375 U6.P6@68.6,65.075
  Top Layer w0.127: 68.406,69.075 v1(68.406,70.5)
  Signal Layer 3 w0.1: P2.13@7.975,68 8.975,67 11.025,67
  Signal Layer 3 w0.12: 11.025,67 14.025,67 14.175,67.15 18.475,67.15 20.575,69.25 53.975,69.25 54.525,69.8 64.525,69.8 64.98,69.345 66.095,69.345 67.25,70.5 v1(68.406,70.5)
STMOD#14-PWM: P2.14 U6.H14 | length 58.6
  Top Layer w0.1: 59.175,62.525 59.295,62.525 59.545,62.775 60.125,62.775 61.4,61.5 62.875,61.5 63.2,61.175 U6.H14@63.4,61.175
  Top Layer w0.12: v1(23.05,65.75) 35.825,65.75 38.275,63.3 55.5,63.3 55.825,62.975 56.125,62.975
  Top Layer w0.127: 56.125,62.975 58.175,62.975 58.625,62.525 59.175,62.525
  Signal Layer 3 w0.1: P2.14@7.975,66 8.975,65 11.025,65
  Signal Layer 3 w0.12: 11.025,65 11.4,64.625 21.925,64.625 v1(23.05,65.75)
T_JTDI: CN7.10 R148.1 U6.A11 U34.1 | length 105
  Top Layer w0.1: 62.375,52.95 65.35,55.925 U6.A11@65.35,56.625
  Top Layer w0.12: CN7.10@7.543,24.069 7.549,24.075 U34.1@9.663,24.075 v1(9.663,23.538) ; v1(49.625,51.969) 56.621,51.969 56.625,51.973
  Top Layer w0.127: 56.625,51.973 61.627,51.973 62.356,52.702 62.356,52.931 62.375,52.95
  Signal Layer 3 w0.12: v1(15.55,15.85) 17.175,15.85 18.375,14.65 45.525,14.65 47.125,16.25 v1(49.625,16.25)
  Bottom Layer w0.12: v1(9.663,23.538) 9.663,20.612 12.125,18.15 15.5,18.15 16.234,17.416 16.234,16.534 v1(15.55,15.85) R148.1@15,15.85 ; v1(49.625,16.25) v1(49.625,51.969)
T_NRSTa: R108.2 U13.P3 | length 106.6
  Top Layer w0.12: R108.2@14.711,24.239 16.414,24.239 v1(16.425,24.25) ; U13.P3@119.133,24.777 v1(119.458,24.452)
  Signal Layer 3 w0.1: 109.908,24.922 116.241,24.922 116.456,24.707 117.672,24.707 117.815,24.85 119.06,24.85 v1(119.458,24.452)
  Signal Layer 3 w0.12: v1(16.425,24.25) 18.05,25.875 63,25.875 63.953,24.922 109.908,24.922
T_PWR_EN: R127.1 U13.R5 U23.4 | length 20
  Top Layer w0.12: R127.1@108.111,14.064 U23.4@109.761,14.064 110.114,14.064 111.75,15.7 v1(114.65,15.7) ; U13.R5@119.783,26.077 v1(120.108,25.752)
  Bottom Layer w0.12: v1(114.65,15.7) 114.65,16.55 120.108,22.008 v1(120.108,25.752)
T_PWR_EXT: R107.2 R109.2 U13.R4 | length 2.8
  Top Layer w0.127: U13.R4@119.783,25.427 120.27,24.939 R107.2@121.311,24.939 R109.2@121.311,23.864
T_SWCLK: CN7.6 JP2.1 R104.1 R153.1 U6.A12 U16.3 | length 97
  Top Layer w0.1: 59.175,52.85 61.55,52.85 64.7,56 U6.A12@64.7,56.625
  Top Layer w0.12: CN7.6@7.543,26.609 9.641,26.609 10,26.25 11.825,26.25 12.211,25.864 U16.3@12.211,25.786 ; U16.3@12.211,25.389 U16.3@12.211,25.786 ; JP2.1@21.171,32.385 16.111,27.325 14.3,27.325 13.811,26.836 R104.1@13.811,26.739 13.164,26.739 v1(12.7,26.275) U16.3@12.211,25.786 ; v1(21.6,48.25) 40.45,48.25 45.053,52.853 56.872,52.853
  Top Layer w0.127: 56.872,52.853 56.875,52.85 59.175,52.85
  Signal Layer 3 w0.12: v1(12.7,26.275) 12.7,25.2 14.275,23.625 14.275,15.225 16.05,13.45 16.05,12.1 v1(15.55,11.6)
  Bottom Layer w0.12: R153.1@15,11.6 v1(15.55,11.6) ; JP2.1@21.171,32.385 21.171,39.021 21.6,39.45 v1(21.6,48.25)
T_SWCLKa: R104.2 U13.M11 | length 106.6
  Top Layer w0.12: R104.2@14.711,26.739 14.722,26.75 v1(16.55,26.75) ; v1(117.508,30.302) U13.M11@117.833,29.977
  Signal Layer 3 w0.12: v1(16.55,28.375) 41.102,28.375 41.107,28.38 41.443,28.38 41.448,28.375 41.752,28.375 41.757,28.38 42.093,28.38 42.098,28.375 43.075,28.375 44.025,29.325 58.55,29.325 59.225,30 66.875,30 67.425,29.45 69.075,29.45 70.225,30.6 107.875,30.6 108.418,30.057 117.263,30.057 v1(117.508,30.302)
  Bottom Layer w0.12: v1(16.55,26.75) v1(16.55,28.375)
T_SWDIO: CN7.4 JP2.2 R103.1 R152.1 U6.B13 U16.4 | length 97.5
  Top Layer w0.1: 59.175,53.1 59.4,53.1 60.375,54.075 v1(61.3,54.075)
  Top Layer w0.12: CN7.4@7.543,27.879 11.81,27.879 12.211,27.478 U16.4@12.211,27.451 ; U16.4@12.211,27.089 U16.4@12.211,27.451 ; JP2.2@18.631,32.385 16.971,30.725 14.775,30.725 13.811,29.761 R103.1@13.811,27.939 v1(12.7,27.939) U16.4@12.211,27.451 ; v1(21.171,48.725) 39.55,48.725 43.925,53.1 56.625,53.1
  Top Layer w0.127: 56.625,53.1 59.175,53.1 ; v2(63.725,56.95) U6.B13@64.05,57.275
  Signal Layer 1 w0.1: v1(61.3,54.075) 61.1,54.275 61.1,55.4 61.25,55.55 61.25,56.3 61.9,56.95 v2(63.725,56.95)
  Signal Layer 3 w0.12: v1(12.7,27.939) 12.175,27.414 12.175,24.875 12.618,24.432 12.618,15.582 v1(15.55,12.65)
  Bottom Layer w0.12: R152.1@15,12.65 v1(15.55,12.65) ; JP2.2@18.631,32.385 18.631,37.406 21.171,39.946 v1(21.171,48.725)
T_SWDIO_IN: R97.1 U13.N12 | length 3.2
  Top Layer w0.12: U13.N12@118.483,30.627 118.808,30.952 120.202,30.952 120.689,31.439 R97.1@121.311,31.439
T_SWDIOa: R97.2 R103.2 U13.L2 | length 125.8
  Top Layer w0.12: R103.2@14.711,27.939 14.722,27.95 v1(15.8,27.95) ; U13.L2@117.183,24.127 v1(117.508,23.802) ; R97.2@122.211,31.439 v1(122.9,31.439)
  Signal Layer 3 w0.1: 109.908,23.802 113.049,23.802 113.444,23.407 114.422,23.407 114.817,23.802 v1(117.508,23.802)
  Signal Layer 3 w0.12: v1(15.65,22.65) 16.275,22.65 18.9,25.275 24.375,25.275 26.25,23.4 69.25,23.4 70.35,24.5 104.425,24.5 105.123,23.802 109.908,23.802 ; v1(117.508,23.802) v1(122.898,23.802)
  Bottom Layer w0.12: v1(15.65,22.65) 15.645,22.655 15.645,24.345 16.275,24.975 16.275,26.35 15.8,26.825 v1(15.8,27.95) ; v1(122.898,23.802) v1(122.9,31.439)
T_SWO: CN7.8 R106.1 R147.1 U6.A6 U16.1 | length 100.4
  Top Layer w0.1: 66.05,51.722 66.05,53.4 66.375,53.725 67.65,53.725 68.6,54.675 U6.A6@68.6,56.625
  Top Layer w0.12: CN7.8@7.543,25.339 7.593,25.389 U16.1@10.911,25.389 10.911,24.589 11.075,24.425 12.525,24.425 13.125,25.025 v1(13.125,25.489) R106.1@13.811,25.489 ; v1(16.4,47.4) 41.14,47.4 41.82,48.08 63.605,48.08 66.375,50.85 66.375,51.397
  Top Layer w0.127: 66.05,51.722 66.375,51.397
  Signal Layer 3 w0.12: v1(13.125,25.489) 14.625,23.989 14.625,17.825 v1(15.55,16.9)
  Bottom Layer w0.12: v1(13.125,25.489) 13.125,38.125 16.4,41.4 v1(16.4,47.4) ; R147.1@15,16.9 v1(15.55,16.9)
T_SWOa: R106.2 U13.D12 | length 103
  Top Layer w0.12: R106.2@14.711,25.489 v1(15.311,25.489) ; v1(112.308,30.952) U13.D12@112.633,30.627
  Signal Layer 3 w0.12: v1(15.311,29.3) 33.2,29.3 42.8,29.3 44.1,30.6 44.325,30.825 69.025,30.825 69.675,31.475 108.65,31.475 109.173,30.952 109.908,30.952 v1(112.308,30.952)
  Bottom Layer w0.12: v1(15.311,25.489) v1(15.311,29.3)
T_VCP_RX: CN7.13 R114.2 U6.K13 U18.1 | length 108.2
  Top Layer w0.127: CN7.13@3.479,21.529 5.201,21.529 6.091,20.639 U18.1@10.911,20.639 10.911,19.589 11.25,19.25 v1(13.825,19.25) 13.825,19.976 R114.2@13.811,19.989 ; v2(63.725,62.8) U6.K13@64.05,62.475
  Signal Layer 1 w0.1: v1(57.875,66.875) 57.875,66.55 58.13,66.295 58.585,66.295 58.88,66 60.525,66 v2(63.725,62.8)
  Signal Layer 3 w0.12: v1(18.875,62.595) 31.005,62.595 31.275,62.325 32.802,62.325 32.807,62.32 51.42,62.32 55.975,66.875 v1(57.875,66.875)
  Bottom Layer w0.12: v1(13.825,19.25) 12.695,20.38 12.695,22.395 13.581,23.282 13.581,36.926 18.875,42.219 v1(18.875,62.595)
T_VCP_TX: CN7.14 R110.1 U6.L14 U18.3 | length 97.1
  Top Layer w0.1: 59.175,64.075 60.4,64.075 61.675,62.8 63.075,62.8 U6.L14@63.4,63.125
  Top Layer w0.12: CN7.14@7.543,21.529 11.746,21.529 U18.3@12.211,21.064 ; U18.3@12.211,20.639 U18.3@12.211,21.064 ; R110.1@13.725,21.175 13.675,21.125 v1(13.1,21.125) 12.211,21.125 U18.3@12.211,21.064
  Top Layer w0.127: v1(56.3,65.125) 57.35,64.075 59.175,64.075
  Signal Layer 3 w0.12: v1(19.35,62.075) 19.63,62.355 30.906,62.355 31.176,62.085 32.703,62.085 32.708,62.08 51.519,62.08 54.564,65.125 v1(56.3,65.125)
  Bottom Layer w0.127: v1(13.1,21.125) 13.1,22.456 13.825,23.181 13.825,36.825 19.35,42.35 v1(19.35,62.075)
TD_N: R76.1 T3.3 U9.20 | length 27.1
  Top Layer w0.13: v1(113.525,64.45) 114.281,63.694 T3.3@114.281,63.279 ; R76.1@115.125,45.275 v1(115.125,45.925) 116.059,46.859 116.059,47.3 116,47.36 U9.20@116,47.85
  Bottom Layer w0.13: v1(113.525,64.45) 113.202,64.127 113.202,63.292 112.906,62.996 112.906,50.779 112.7,50.573 112.7,45.95 113.344,45.306 115.392,45.306 115.472,45.386 115.472,45.578 v1(115.125,45.925)
TD_P: R77.1 T3.1 U9.21 | length 28
  Top Layer w0.13: T3.1@111.741,63.279 111.741,63.694 v1(112.498,64.45) ; R77.1@116.2,45.275 v1(116.2,45.925) 116.2,46.461 116.44,46.702 116.44,47.3 116.5,47.36 U9.21@116.5,47.85
  Bottom Layer w0.13: v1(112.498,64.45) 112.821,64.127 112.821,63.45 112.525,63.154 112.525,50.937 112.319,50.731 112.319,45.792 113.186,44.925 115.55,44.925 115.853,45.228 115.853,45.578 v1(116.2,45.925)
USB_DEV_HS_CN_N: CN15.2 U29.5 | length 2.6
  Top Layer w0.155: CN15.2@114.125,4.15 114.125,4.902 114.259,5.037 114.259,6.214 114.186,6.287 U29.5@114.186,6.664
USB_DEV_HS_CN_P: CN15.3 U29.6 | length 2.6
  Top Layer w0.155: U29.6@114.686,6.664 114.686,6.287 114.64,6.241 114.64,5.037 114.775,4.902 CN15.3@114.775,4.15
USB_DEV_HS_N: U13.R14 U29.2 | length 28.4
  Top Layer w0.155: U29.2@114.186,7.964 v1(114.186,8.711) ; U13.R14@119.783,31.927 v1(120.252,31.927)
  Bottom Layer w0.155: v1(114.186,8.711) 114.365,8.89 114.365,10.179 115.769,11.583 115.769,15.794 121.475,21.5 121.475,25.95 120.925,26.501 120.925,31.861 120.725,32.061 120.386,32.061 v1(120.252,31.927)
USB_DEV_HS_P: U13.R15 U29.1 | length 29.2
  Top Layer w0.155: U29.1@114.686,7.964 114.686,8.461 v1(114.925,8.7) ; U13.R15@119.783,32.577 v1(120.252,32.577)
  Bottom Layer w0.155: v1(114.925,8.7) 114.746,8.879 114.746,10.021 116.15,11.425 116.15,15.636 121.856,21.342 121.856,26.108 121.306,26.658 121.306,32.019 120.883,32.442 120.386,32.442 v1(120.252,32.577)
USB_FS_DM: CN14.2 U6.C15 U25.3 | length 104.8
  Top Layer w0.155: v1(51.95,58) 52.15,58.2 52.15,58.514 52.786,59.15 56.05,59.15 57.409,57.791 62.413,57.791 62.548,57.925 U6.C15@62.75,57.925 ; CN14.2@84.425,4.125 84.425,4.878 84.291,5.012 84.291,6.348 84.09,6.548 84.09,8.825 84.315,9.05 U25.3@84.725,9.05 ; v1(84.55,9.75) 84.55,9.225 U25.3@84.725,9.05 ; U25.3@85.05,9.05 U25.3@84.725,9.05
  Bottom Layer w0.155: v1(51.95,58) 52.197,57.753 52.197,57.225 52.05,57.078 52.05,13.2 49.994,11.144 49.994,9.606 51.425,8.175 76.4,8.175 77.025,8.8 81.011,8.8 81.467,8.344 83.583,8.344 84.09,8.852 84.09,9.625 84.216,9.75 v1(84.55,9.75)
USB_FS_DP: CN14.3 U6.B15 U25.4 | length 102.9
  Top Layer w0.155: v1(52.825,57.95) 52.55,58.225 52.55,58.375 52.944,58.769 55.892,58.769 57.252,57.41 62.413,57.41 62.548,57.275 U6.B15@62.75,57.275 ; U25.4@82.75,9.05 U25.4@83.075,9.05 ; v1(83.25,9.75) 83.25,9.225 U25.4@83.075,9.05 ; CN14.3@83.775,4.125 83.775,4.878 83.91,5.012 83.91,6.19 83.709,6.391 83.709,8.825 83.485,9.05 U25.4@83.075,9.05
  Bottom Layer w0.155: v1(52.825,57.95) 52.578,57.703 52.578,57.067 52.431,56.92 52.431,13.042 50.375,10.986 50.375,9.764 51.583,8.556 76.242,8.556 76.411,8.725 76.867,9.181 81.169,9.181 81.625,8.725 83.425,8.725 83.709,9.009 83.709,9.625 83.584,9.75 v1(83.25,9.75)
USB_FS_ID: CN14.4 U6.C14 U25.6 | length 94
  Top Layer w0.1: 59.002,56.777 62.504,56.777 62.632,56.904 62.829,56.904 63.075,57.15 63.075,57.6 U6.C14@63.4,57.925
  Top Layer w0.127: v1(53.675,57.7) 54.127,58.152 55.248,58.152 56.623,56.777 59.002,56.777 ; v1(81.483,7.167) 82.733,7.167 U25.6@82.75,7.15 83.125,7.15 CN14.4@83.125,4.125
  Signal Layer 3 w0.127: v1(53.616,12.558) 54.225,11.95 79.775,11.95 81.483,10.242 v1(81.483,7.167)
  Bottom Layer w0.127: v1(53.616,12.558) 53.616,33.159 53,33.775 53,53.875 54.275,55.15 54.275,57.1 v1(53.675,57.7)
USB_FS_OVCR: R116.2 U6.B7 | length 63
  Top Layer w0.1: v1(67.375,54.425) 67.375,55.105 67.625,55.355 67.625,56.95 U6.B7@67.95,57.275
  Top Layer w0.12: R116.2@89.9,17.125 v1(89.9,17.875)
  Signal Layer 3 w0.12: v1(67.975,17.575) 89.6,17.575 v1(89.9,17.875)
  Bottom Layer w0.12: v1(67.375,54.425) 67.375,53.825 67.975,53.225 v1(67.975,17.575)
USB_FS_PWR_EN: R128.1 U6.R5 | length 84.9
  Top Layer w0.1: U6.R5@69.25,65.725 69.25,69.065
  Top Layer w0.12: R128.1@95.625,13.025 v1(95.625,13.75)
  Top Layer w0.127: 69.26,69.075 v1(69.26,69.85)
  Signal Layer 3 w0.1: 70.035,69.075 70.36,68.75 74.425,68.75 75.425,67.75
  Signal Layer 3 w0.12: v1(69.26,69.85) 70.035,69.075 ; 75.425,67.75 75.485,67.69 93.635,67.69 v1(94.025,67.3)
  Bottom Layer w0.12: v1(94.025,67.3) 95.625,65.7 v1(95.625,13.75)
USB_FS_VBUS: C112.1 CN14.1 D11.1 JP7.3 R135.2 U6.D13 U24.1 U25.1 | length 26.5
  Top Layer w0.127: v2(63.725,58.25) U6.D13@64.05,58.575
  Top Layer w0.2: R135.2@76.65,3.95 v1(77.275,3.95)
  Top Layer w0.4: CN14.1@85.075,4.125 85.075,7.125 U25.1@85.05,7.15 v1(86.25,7.15) ; v1(87.9,15.05) 87.9,13.9 88.1,13.7 C112.1@88.375,13.7 88.525,13.85 U24.1@90.925,13.85
  Top Layer w0.5: JP7.3@101.915,5.945 v1(101.915,10.778)
  Top Layer w0.508: v1(105.014,28.938) D11.1@105.014,29.944
  Signal Layer 1 w0.1: v1(53.7,55.875) 59.375,55.875 61.75,58.25 v2(63.725,58.25)
  other v1: 101.915,10.275
uSD_Detect: CN2.10 R3.1 U6.H3 | length 101
  Top Layer w0.12: v1(31,82.6) R3.1@37.35,82.6 CN2.10@39.975,82.6
  Top Layer w0.127: U6.H3@70.55,61.175 v2(70.875,60.85)
  Signal Layer 1 w0.1: v2(70.875,60.85) 70.875,60.844 71.144,60.575 72.525,60.575 73.75,59.35 v1(73.75,58.5)
  Signal Layer 3 w0.12: v1(31.225,49.325) 31.65,48.9 45.875,48.9 46.85,49.875 57.625,49.875 58.475,49.025 71.575,49.025 71.91,49.361 v1(74.535,49.361)
  Bottom Layer w0.12: v1(31,82.6) 31,57.825 31.225,57.6 v1(31.225,49.325) ; v1(73.75,58.5) 73.75,57.625 74.535,56.84 v1(74.535,49.361)
USER_LED1: R144.1 U6.M2 | length 97.9
  Top Layer w0.1: U6.M2@71.2,63.775 71.525,63.45 72.075,63.45 72.475,63.85 74.05,63.85 74.9,64.7 75.425,64.7
  Top Layer w0.12: 75.425,64.7 82.95,64.7 v1(86.55,61.1)
  Signal Layer 3 w0.12: v1(86.55,61.1) 86.58,61.07 96.28,61.07 96.8,60.55 142.15,60.55 142.67,61.07 v1(144.27,61.07)
  Bottom Layer w0.12: v1(144.27,61.07) 144.27,44.78 144.975,44.075 R144.1@149.925,44.075
USER_LED2: R143.1 U6.M1 | length 95
  Top Layer w0.1: U6.M1@71.85,63.775 72.05,63.775 72.375,64.1 74,64.1 74.85,64.95 75.425,64.95
  Top Layer w0.12: 75.425,64.95 83.273,64.95 86.748,61.475 v1(87.075,61.475)
  Signal Layer 3 w0.12: v1(87.075,61.475) 96.475,61.475 97,60.95 114.025,60.95 114.55,61.475 v1(144.775,61.475)
  Bottom Layer w0.12: v1(144.775,61.475) 144.775,47.4 145.875,46.3 R143.1@149.925,46.3
VDD_ETH: C33.2 R42.2 SB9.2 T3.2 | length 16.4
  Top Layer w0.381: v1(111.55,62.05) 112.326,62.05 112.711,61.664 C33.2@113.011,61.664 T3.2@113.011,63.279 ; SB9.2@117.65,60 117.65,59.85 117.564,59.764 R42.2@119.361,59.764 119.625,59.501 v1(119.625,58.875)
  Signal Layer 2 w0.6: v1(111.55,62.05) 112.45,62.95 115.55,62.95 v1(119.625,58.875)
VDD_MCU: C124.2 C125.2 C126.2 C127.2 C128.2 C129.2 C131.2 C133.2 C134.2 C135.2 C137.2 JP1.1 L2.1 L5.1 SB1.1 SB11.1 U6.D5 U6.D11 U6.E4 U6.E12 U6.G4 U6.H12 U6.K4 U6.L12 U6.M5 U6.M9 | length 18.1
  Top Layer w0.127: v1(64.375,58.9) U6.E12@64.7,59.225 ; v1(64.375,61.5) U6.H12@64.7,61.175 ; v1(64.375,63.45) U6.L12@64.7,63.125 ; v1(65.025,58.25) U6.D11@65.35,58.575 ; v1(66.325,64.1) U6.M9@66.65,63.775 ; U6.D5@69.25,58.575 v1(69.575,58.25) ; U6.M5@69.25,63.775 v1(69.575,64.1) ; U6.E4@69.9,59.225 v1(70.225,58.9) ; U6.G4@69.9,60.525 v1(70.225,60.2) ; U6.K4@69.9,62.475 v1(70.225,62.8)
  Top Layer w0.35: v1(53.45,60.725) SB11.1@54.725,60.725 ; v1(61.3,70.825) 61.3,70.125 61.35,70.075 ; L2.1@76.825,61.725 v1(77.675,61.725)
  Bottom Layer w0.127: C125.2@63.7,63.45 v1(64.375,63.45) ; C128.2@63.725,61.5 v1(64.375,61.5) ; C133.2@64.35,58.225 64.375,58.25 v1(64.375,58.9) ; C137.2@65.025,56.675 65.025,57.575 v1(65.025,58.25) ; v1(66.325,64.1) 66.325,64.75 C124.2@66.35,64.775 ; C126.2@69.525,63.375 69.575,63.425 v1(69.575,64.1) ; C134.2@69.575,57.6 v1(69.575,58.25) ; C129.2@69.7,59.95 69.95,60.2 v1(70.225,60.2) 70.725,60.7 71.9,60.7 L5.1@72.7,61.5 ; C127.2@70.175,62.2 70.225,62.25 v1(70.225,62.8) ; v1(70.225,58.9) 70.575,58.9 C131.2@70.825,58.65
VDD_SDC: C23.1 C47.1 C54.1 L3.1 SB2.1 SB13.2 SB18.1 SB20.1 SB21.1 U6.G2 | length 12.3
  Top Layer w0.127: L3.1@75.775,58.65 L3.1@76.075,58.35
  Top Layer w0.35: C47.1@55.575,54.025 SB18.1@57.4,54.025 ; v1(61.975,71.7) 61.975,71.4 62.15,71.225 C23.1@62.775,71.225 SB2.1@62.775,69.725 ; C54.1@68.825,49.8 68.825,51.05 SB21.1@70.55,51.05 ; C54.1@68.85,49.775 v1(69.475,49.775) ; U6.G2@71.2,60.525 v1(71.525,60.2) ; v1(75,59.875) 75.775,59.1 L3.1@75.775,58.65 ; L3.1@76.075,58.35 77.85,58.35
  other v1: 56.325,54.025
